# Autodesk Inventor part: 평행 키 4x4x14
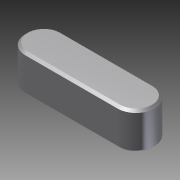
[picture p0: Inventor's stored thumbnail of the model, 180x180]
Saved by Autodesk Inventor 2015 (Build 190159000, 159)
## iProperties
Created: 2024-12
Part Number: 평행 키 4x4x14
Material: 일반
Document SubType Name: Modeling
Designer: 10401
Density: 1 g/cm^3
Appearance: 기본값
Author: 10401
Author: jhkim
Description: 키 및 해당 키홈
Creation Date: 2024-12-12
Sending System: Autodesk Inventor 2025
Preprocessor: ST-DEVELOPER v20
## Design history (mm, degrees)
node "평행 키 4x4x141"
body "Solid1"
node "기준1"
